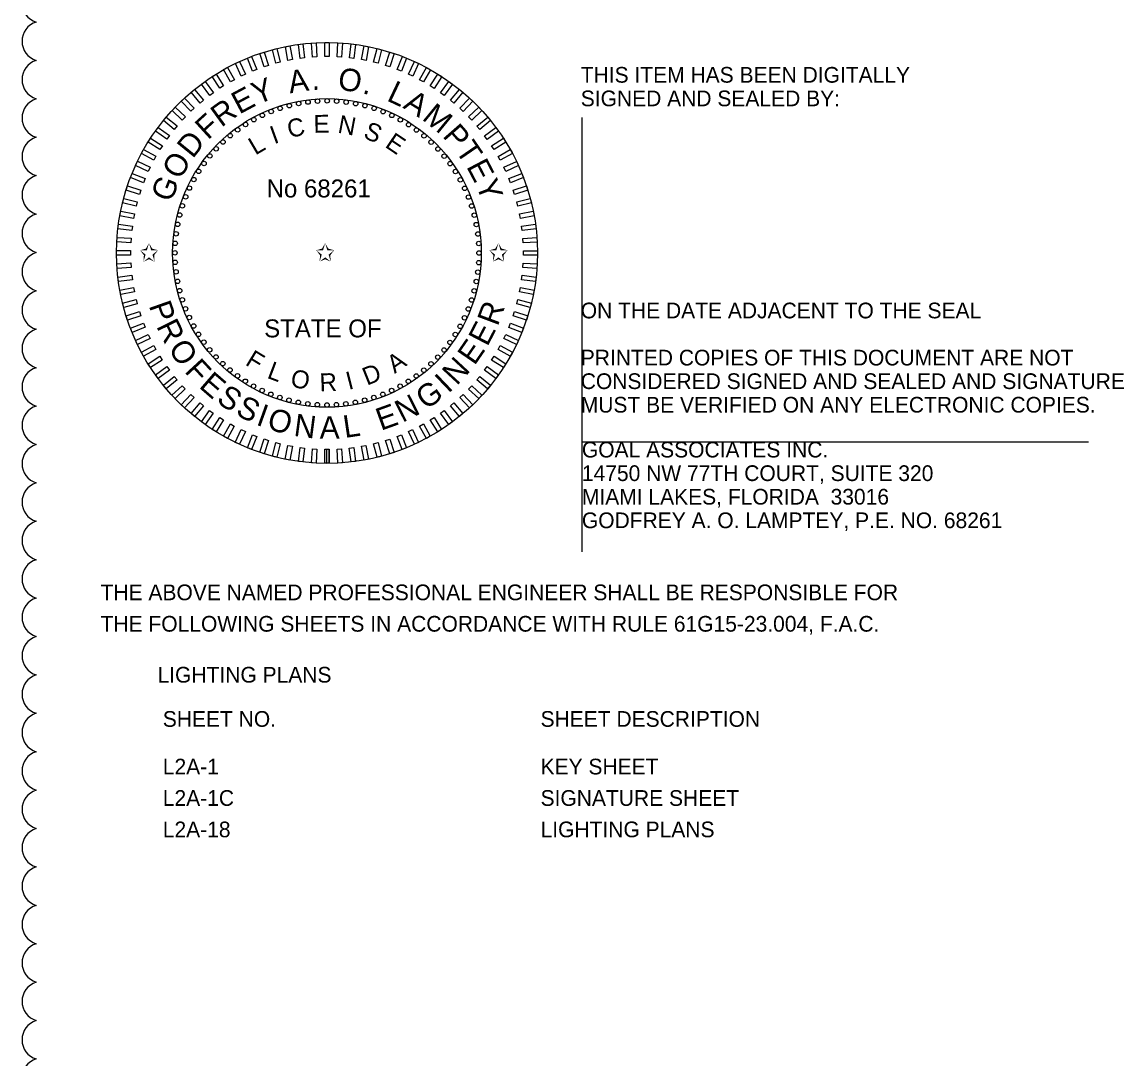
# Model space of a CAD drawing. Extents: x -811 to 10319, y -2309 to 9962.
# Drawn here: x -810.849 to -805.94, y -2224.471 to -2219.851 of the extents above; entities that cross this region are included whole.
import ezdxf

# ---------------------------------------------------------------- set-up
doc = ezdxf.new("R2010")
doc.units = 0
for name, color, linetype in [('AdhocPoint_dp', 7, 'Continuous'), ('PlotBorder_dp', 7, 'Continuous'), ('TextMinor', 7, 'Continuous'), ('TextMisc', 7, 'Continuous'), ('TextShtNo', 7, 'Continuous'), ('TextTitle', 7, 'Continuous')]:
    doc.layers.add(name, color=color, linetype=linetype)

msp = doc.modelspace()

# ---------------------------------------------------------------- linework, layer by layer
at = {"layer": 'AdhocPoint_dp'}
for p, q in [((-808.3546, -2220.2766), (-808.3546, -2222.2113)), ((-808.3546, -2221.7213), (-806.0979, -2221.7213))]:
    msp.add_line(p, q, dxfattribs=at)
at = {"layer": 'TextMinor'}
for radius in [0.9375, 0.6875]:
    msp.add_circle((-809.4901, -2220.88), radius, dxfattribs=at)
at = {"layer": 'TextShtNo'}
for p, q in [((-809.5001, -2221.8175), (-809.5003, -2221.755)), ((-809.4901, -2221.8175), (-809.4903, -2221.755)), ((-809.4801, -2221.8174), (-809.4803, -2221.7549))]:
    msp.add_line(p, q, dxfattribs=at)
for points in [[(-809.6441, -2220.0185), (-809.6639, -2220.0223), (-809.6756, -2219.961), (-809.6558, -2219.9572)], [(-809.5897, -2220.0105), (-809.6097, -2220.0131), (-809.6175, -2219.9511), (-809.5975, -2219.9486)], [(-809.5349, -2220.006), (-809.555, -2220.0073), (-809.559, -2219.945), (-809.5388, -2219.9437)], [(-809.4799, -2220.0049), (-809.5001, -2220.0049), (-809.5001, -2219.9425), (-809.4799, -2219.9425)], [(-809.425, -2220.0073), (-809.4452, -2220.006), (-809.4412, -2219.9437), (-809.4211, -2219.945)], [(-809.3703, -2220.0131), (-809.3904, -2220.0106), (-809.3825, -2219.9486), (-809.3625, -2219.9512)], [(-809.3162, -2220.0223), (-809.336, -2220.0186), (-809.3243, -2219.9572), (-809.3045, -2219.961)], [(-809.8028, -2220.0626), (-809.8215, -2220.0701), (-809.8445, -2220.012), (-809.8258, -2220.0046)], [(-809.7508, -2220.0446), (-809.77, -2220.0508), (-809.7893, -2219.9915), (-809.7701, -2219.9852)], [(-809.6979, -2220.0299), (-809.7174, -2220.0349), (-809.7329, -2219.9744), (-809.7134, -2219.9694)], [(-809.2626, -2220.0349), (-809.2822, -2220.0299), (-809.2667, -2219.9695), (-809.2471, -2219.9745)], [(-809.21, -2220.0509), (-809.2292, -2220.0447), (-809.2099, -2219.9853), (-809.1907, -2219.9915)], [(-809.1585, -2220.0701), (-809.1773, -2220.0627), (-809.1543, -2220.0046), (-809.1355, -2220.0121)], [(-809.9027, -2220.1083), (-809.9204, -2220.118), (-809.9505, -2220.0633), (-809.9328, -2220.0535)], [(-809.8535, -2220.0839), (-809.8717, -2220.0925), (-809.8983, -2220.036), (-809.8801, -2220.0274)], [(-809.1083, -2220.0925), (-809.1266, -2220.0839), (-809.1, -2220.0274), (-809.0817, -2220.036)], [(-809.0596, -2220.1181), (-809.0773, -2220.1083), (-809.0473, -2220.0536), (-809.0296, -2220.0634)], [(-809.9504, -2220.1357), (-809.9674, -2220.1465), (-810.0009, -2220.0938), (-809.9838, -2220.083)], [(-809.0127, -2220.1466), (-809.0297, -2220.1358), (-808.9962, -2220.0831), (-808.9792, -2220.0939)], [(-810.04, -2220.1992), (-810.0556, -2220.2121), (-810.0954, -2220.164), (-810.0798, -2220.1511)], [(-809.9962, -2220.1661), (-810.0125, -2220.1779), (-810.0492, -2220.1274), (-810.0329, -2220.1155)], [(-808.9676, -2220.178), (-808.9839, -2220.1662), (-808.9472, -2220.1156), (-808.9308, -2220.1275)], [(-808.9245, -2220.2122), (-808.9401, -2220.1994), (-808.9003, -2220.1512), (-808.8847, -2220.1641)], [(-810.0817, -2220.2351), (-810.0964, -2220.2489), (-810.1392, -2220.2034), (-810.1244, -2220.1896)], [(-808.8837, -2220.2491), (-808.8984, -2220.2352), (-808.8557, -2220.1897), (-808.841, -2220.2035)], [(-810.121, -2220.2735), (-810.1348, -2220.2882), (-810.1804, -2220.2455), (-810.1665, -2220.2308)], [(-808.8453, -2220.2884), (-808.8591, -2220.2737), (-808.8136, -2220.2309), (-808.7998, -2220.2456)], [(-810.1579, -2220.3143), (-810.1707, -2220.3299), (-810.2188, -2220.2901), (-810.206, -2220.2745)], [(-808.8094, -2220.33), (-808.8223, -2220.3145), (-808.7742, -2220.2747), (-808.7613, -2220.2902)], [(-810.192, -2220.3574), (-810.2039, -2220.3737), (-810.2544, -2220.337), (-810.2426, -2220.3207)], [(-808.7762, -2220.3739), (-808.7881, -2220.3575), (-808.7376, -2220.3208), (-808.7257, -2220.3372)], [(-810.2235, -2220.4025), (-810.2343, -2220.4195), (-810.287, -2220.3861), (-810.2762, -2220.369)], [(-808.7459, -2220.4197), (-808.7567, -2220.4026), (-808.7039, -2220.3692), (-808.6931, -2220.3862)], [(-810.252, -2220.4495), (-810.2617, -2220.4672), (-810.3164, -2220.4371), (-810.3067, -2220.4194)], [(-808.7184, -2220.4673), (-808.7281, -2220.4496), (-808.6734, -2220.4196), (-808.6637, -2220.4373)], [(-810.2775, -2220.4982), (-810.2861, -2220.5164), (-810.3426, -2220.4898), (-810.334, -2220.4716)], [(-808.694, -2220.5166), (-808.7026, -2220.4983), (-808.6461, -2220.4718), (-808.6375, -2220.49)], [(-810.3, -2220.5484), (-810.3074, -2220.5671), (-810.3654, -2220.5441), (-810.358, -2220.5254)], [(-808.6728, -2220.5673), (-808.6802, -2220.5485), (-808.6222, -2220.5256), (-808.6147, -2220.5443)], [(-810.3192, -2220.5999), (-810.3254, -2220.6191), (-810.3848, -2220.5998), (-810.3786, -2220.5806)], [(-808.6548, -2220.6192), (-808.661, -2220.6), (-808.6016, -2220.5808), (-808.5954, -2220.5999)], [(-810.3351, -2220.6525), (-810.3401, -2220.672), (-810.4006, -2220.6565), (-810.3956, -2220.637)], [(-808.64, -2220.6722), (-808.6451, -2220.6527), (-808.5846, -2220.6371), (-808.5796, -2220.6567)], [(-810.3477, -2220.706), (-810.3515, -2220.7258), (-810.4129, -2220.7141), (-810.4091, -2220.6943)], [(-808.6287, -2220.726), (-808.6325, -2220.7062), (-808.5711, -2220.6945), (-808.5673, -2220.7143)], [(-810.357, -2220.7602), (-810.3595, -2220.7802), (-810.4215, -2220.7724), (-810.4189, -2220.7524)], [(-808.6207, -2220.7804), (-808.6232, -2220.7604), (-808.5613, -2220.7525), (-808.5588, -2220.7726)], [(-810.3628, -2220.8148), (-810.3641, -2220.835), (-810.4264, -2220.8311), (-810.4251, -2220.8109)], [(-808.6162, -2220.8352), (-808.6174, -2220.815), (-808.5551, -2220.8111), (-808.5539, -2220.8313)], [(-810.3652, -2220.8698), (-810.3652, -2220.89), (-810.4276, -2220.89), (-810.4276, -2220.8698)], [(-808.6151, -2220.8901), (-808.6151, -2220.87), (-808.5527, -2220.87), (-808.5527, -2220.8901)], [(-810.3641, -2220.9247), (-810.3628, -2220.9449), (-810.4251, -2220.9488), (-810.4264, -2220.9287)], [(-808.6175, -2220.9451), (-808.6162, -2220.9249), (-808.5539, -2220.9288), (-808.5551, -2220.949)], [(-810.3595, -2220.9795), (-810.357, -2220.9995), (-810.4189, -2221.0074), (-810.4215, -2220.9873)], [(-808.6233, -2220.9997), (-808.6207, -2220.9797), (-808.5588, -2220.9875), (-808.5613, -2221.0076)], [(-810.3516, -2221.0339), (-810.3478, -2221.0537), (-810.4091, -2221.0654), (-810.4129, -2221.0456)], [(-808.6325, -2221.0539), (-808.6287, -2221.0341), (-808.5674, -2221.0458), (-808.5712, -2221.0656)], [(-810.3402, -2221.0877), (-810.3352, -2221.1073), (-810.3957, -2221.1228), (-810.4007, -2221.1032)], [(-808.6451, -2221.1074), (-808.6401, -2221.0879), (-808.5796, -2221.1034), (-808.5846, -2221.123)], [(-810.3255, -2221.1407), (-810.3192, -2221.1599), (-810.3786, -2221.1792), (-810.3849, -2221.16)], [(-808.6611, -2221.16), (-808.6548, -2221.1408), (-808.5954, -2221.1601), (-808.6017, -2221.1793)], [(-810.3075, -2221.1926), (-810.3, -2221.2114), (-810.3581, -2221.2344), (-810.3655, -2221.2156)], [(-808.6803, -2221.2115), (-808.6729, -2221.1928), (-808.6148, -2221.2158), (-808.6222, -2221.2345)], [(-810.2862, -2221.2433), (-810.2776, -2221.2616), (-810.3341, -2221.2882), (-810.3427, -2221.2699)], [(-808.7027, -2221.2617), (-808.6941, -2221.2435), (-808.6376, -2221.2701), (-808.6462, -2221.2883)], [(-810.2618, -2221.2926), (-810.2521, -2221.3103), (-810.3068, -2221.3403), (-810.3165, -2221.3227)], [(-808.7282, -2221.3104), (-808.7185, -2221.2927), (-808.6638, -2221.3228), (-808.6735, -2221.3405)], [(-810.2344, -2221.3402), (-810.2236, -2221.3573), (-810.2763, -2221.3907), (-810.2871, -2221.3737)], [(-808.7568, -2221.3574), (-808.746, -2221.3404), (-808.6932, -2221.3738), (-808.704, -2221.3909)], [(-810.204, -2221.386), (-810.1922, -2221.4024), (-810.2427, -2221.4391), (-810.2545, -2221.4227)], [(-810.1708, -2221.4299), (-810.158, -2221.4454), (-810.2061, -2221.4852), (-810.2189, -2221.4697)], [(-808.8224, -2221.4456), (-808.8095, -2221.43), (-808.7614, -2221.4698), (-808.7743, -2221.4854)], [(-808.7882, -2221.4025), (-808.7763, -2221.3862), (-808.7258, -2221.4229), (-808.7377, -2221.4392)], [(-810.135, -2221.4715), (-810.1211, -2221.4862), (-810.1667, -2221.529), (-810.1805, -2221.5143)], [(-808.8592, -2221.4864), (-808.8454, -2221.4717), (-808.7999, -2221.5144), (-808.8137, -2221.5291)], [(-810.0965, -2221.5109), (-810.0818, -2221.5247), (-810.1246, -2221.5702), (-810.1393, -2221.5564)], [(-808.8985, -2221.5248), (-808.8838, -2221.511), (-808.8411, -2221.5565), (-808.8558, -2221.5703)], [(-810.0557, -2221.5477), (-810.0402, -2221.5606), (-810.08, -2221.6087), (-810.0955, -2221.5958)], [(-808.9402, -2221.5607), (-808.9247, -2221.5478), (-808.8848, -2221.5959), (-808.9004, -2221.6088)], [(-810.0127, -2221.5819), (-809.9964, -2221.5937), (-810.0331, -2221.6443), (-810.0494, -2221.6324)], [(-809.9676, -2221.6133), (-809.9505, -2221.6241), (-809.984, -2221.6768), (-810.001, -2221.666)], [(-809.0299, -2221.6242), (-809.0128, -2221.6134), (-808.9794, -2221.6661), (-808.9964, -2221.6769)], [(-808.984, -2221.5939), (-808.9677, -2221.582), (-808.931, -2221.6325), (-808.9473, -2221.6444)], [(-809.9206, -2221.6418), (-809.9029, -2221.6516), (-809.933, -2221.7063), (-809.9507, -2221.6966)], [(-809.8719, -2221.6674), (-809.8536, -2221.676), (-809.8802, -2221.7325), (-809.8985, -2221.7239)], [(-809.1268, -2221.676), (-809.1085, -2221.6674), (-809.0819, -2221.7239), (-809.1002, -2221.7325)], [(-809.0775, -2221.6517), (-809.0598, -2221.6419), (-809.0297, -2221.6966), (-809.0474, -2221.7064)], [(-809.8217, -2221.6898), (-809.8029, -2221.6972), (-809.8259, -2221.7553), (-809.8447, -2221.7478)], [(-809.7702, -2221.709), (-809.751, -2221.7152), (-809.7703, -2221.7746), (-809.7895, -2221.7684)], [(-809.7176, -2221.725), (-809.698, -2221.73), (-809.7136, -2221.7905), (-809.7331, -2221.7854)], [(-809.2824, -2221.73), (-809.2628, -2221.725), (-809.2473, -2221.7855), (-809.2668, -2221.7905)], [(-809.2294, -2221.7153), (-809.2102, -2221.7091), (-809.1909, -2221.7685), (-809.2101, -2221.7747)], [(-809.1775, -2221.6973), (-809.1587, -2221.6899), (-809.1357, -2221.7479), (-809.1545, -2221.7553)], [(-809.6641, -2221.7376), (-809.6443, -2221.7414), (-809.656, -2221.8027), (-809.6758, -2221.7989)], [(-809.6099, -2221.7468), (-809.5899, -2221.7493), (-809.5977, -2221.8113), (-809.6177, -2221.8088)], [(-809.5552, -2221.7526), (-809.5351, -2221.7539), (-809.539, -2221.8162), (-809.5592, -2221.8149)], [(-809.5003, -2221.755), (-809.4801, -2221.755), (-809.4801, -2221.8174), (-809.5003, -2221.8174)], [(-809.4453, -2221.7539), (-809.4252, -2221.7526), (-809.4213, -2221.8149), (-809.4414, -2221.8162)], [(-809.3906, -2221.7494), (-809.3705, -2221.7468), (-809.3627, -2221.8088), (-809.3827, -2221.8113)], [(-809.3362, -2221.7414), (-809.3163, -2221.7376), (-809.3046, -2221.7989), (-809.3245, -2221.8027)]]:
    msp.add_lwpolyline(points, close=True, dxfattribs=at)
for centre in [(-809.5745, -2220.2078), (-809.5321, -2220.2038), (-809.4896, -2220.2025), (-809.447, -2220.2039), (-809.4047, -2220.2079), (-809.739, -2220.2499), (-809.6989, -2220.2355), (-809.6581, -2220.2236), (-809.6165, -2220.2144), (-809.3626, -2220.2146), (-809.3211, -2220.2239), (-809.2802, -2220.2358), (-809.2402, -2220.2503), (-809.8527, -2220.3076), (-809.816, -2220.286), (-809.7781, -2220.2667), (-809.2012, -2220.2672), (-809.1633, -2220.2866), (-809.1266, -2220.3083), (-809.9215, -2220.3576), (-809.8879, -2220.3315), (-809.0915, -2220.3322), (-809.0579, -2220.3583), (-809.9535, -2220.3857), (-809.026, -2220.3865), (-810.0118, -2220.4477), (-809.9836, -2220.4158), (-808.9959, -2220.4166), (-808.9678, -2220.4486), (-810.0379, -2220.4813), (-808.9417, -2220.4822), (-810.0835, -2220.5531), (-810.0618, -2220.5165), (-808.9178, -2220.5174), (-808.8962, -2220.5541), (-810.1029, -2220.591), (-808.8769, -2220.592), (-810.1198, -2220.63), (-808.86, -2220.6311), (-810.1343, -2220.6701), (-808.8456, -2220.6711), (-810.1555, -2220.7525), (-810.1462, -2220.7109), (-808.8338, -2220.712), (-808.8245, -2220.7536), (-810.1622, -2220.7945), (-808.8179, -2220.7956), (-810.1662, -2220.8369), (-808.814, -2220.838), (-810.1676, -2220.8794), (-808.8127, -2220.8805), (-810.1663, -2220.9219), (-808.814, -2220.9231), (-810.1623, -2220.9643), (-808.8181, -2220.9654), (-810.1557, -2221.0063), (-810.1464, -2221.0479), (-808.8248, -2221.0075), (-810.1346, -2221.0888), (-808.846, -2221.0898), (-808.8341, -2221.049), (-810.1202, -2221.1288), (-808.8604, -2221.1299), (-810.1034, -2221.1679), (-808.8774, -2221.1689), (-810.0841, -2221.2058), (-810.0624, -2221.2425), (-808.9184, -2221.2434), (-808.8967, -2221.2068), (-810.0385, -2221.2777), (-808.9424, -2221.2786), (-810.0125, -2221.3114), (-808.9685, -2221.3122), (-809.9844, -2221.3433), (-809.9543, -2221.3734), (-809.0268, -2221.3742), (-808.9967, -2221.3441), (-809.9224, -2221.4016), (-809.8888, -2221.4277), (-809.0924, -2221.4284), (-809.0587, -2221.4023), (-809.8536, -2221.4517), (-809.817, -2221.4734), (-809.1642, -2221.4739), (-809.1276, -2221.4523), (-809.7791, -2221.4927), (-809.74, -2221.5096), (-809.7, -2221.5241), (-809.6591, -2221.536), (-809.3222, -2221.5363), (-809.2813, -2221.5244), (-809.2413, -2221.5101), (-809.2022, -2221.4932), (-809.6176, -2221.5453), (-809.5756, -2221.552), (-809.5332, -2221.5561), (-809.4901, -2221.5575), (-809.4481, -2221.5561), (-809.4058, -2221.5522), (-809.3637, -2221.5455)]:
    msp.add_circle(centre, 0.01, dxfattribs=at)
at = {"layer": 'TextTitle'}
for centre in [(-810.7588, -2219.7655), (-810.7588, -2219.9367), (-810.7588, -2220.1078), (-810.7588, -2220.2789), (-810.7588, -2220.45), (-810.7588, -2220.6212), (-810.7588, -2220.7923), (-810.7588, -2220.9634), (-810.7588, -2221.1345), (-810.7588, -2221.3057), (-810.7588, -2221.4768), (-810.7588, -2221.6479), (-810.7588, -2221.819), (-810.7588, -2221.9901), (-810.7588, -2222.1613), (-810.7588, -2222.3324), (-810.7588, -2222.5035), (-810.7588, -2222.6746), (-810.7588, -2222.8458), (-810.7588, -2223.0169), (-810.7588, -2223.188), (-810.7588, -2223.3591), (-810.7588, -2223.5302), (-810.7588, -2223.7014), (-810.7588, -2223.8725), (-810.7588, -2224.0436), (-810.7588, -2224.2147), (-810.7588, -2224.3859), (-810.7588, -2224.557)]:
    msp.add_arc(centre, 0.0897, 107.5, 252.5, dxfattribs=at)

# ---------------------------------------------------------------- texts
at = {"layer": 'PlotBorder_dp'}
for s, p in [('THIS ITEM HAS BEEN DIGITALLY', (-808.3596, -2220.1214)), ('SIGNED AND SEALED BY:', (-808.3596, -2220.2264)), ('ON THE DATE ADJACENT TO THE SEAL', (-808.3596, -2221.1714)), ('PRINTED COPIES OF THIS DOCUMENT ARE NOT ', (-808.3596, -2221.3814)), ('CONSIDERED SIGNED AND SEALED AND SIGNATURE ', (-808.3596, -2221.4864)), ('MUST BE VERIFIED ON ANY ELECTRONIC COPIES.', (-808.3596, -2221.5914)), ('GOAL ASSOCIATES INC.', (-808.3546, -2221.7913)), ('14750 NW 77TH COURT, SUITE 320', (-808.3546, -2221.8963)), ('MIAMI LAKES, FLORIDA  33016', (-808.3546, -2222.0013)), ('GODFREY A. O. LAMPTEY, P.E. NO. 68261', (-808.3546, -2222.1063)), ('THE ABOVE NAMED PROFESSIONAL ENGINEER SHALL BE RESPONSIBLE FOR ', (-810.4987, -2222.4274)), ('THE FOLLOWING SHEETS IN ACCORDANCE WITH RULE 61G15-23.004, F.A.C.', (-810.4987, -2222.5674)), ('LIGHTING PLANS', (-810.245, -2222.7944))]:
    msp.add_text(s, height=0.07, dxfattribs=at).set_placement(p)
at = {"layer": 'TextMisc'}
for s, p in [('SHEET NO.', (-810.2215, -2222.9914)), ('SHEET DESCRIPTION', (-808.5387, -2222.9914)), ('L2A-1', (-810.2215, -2223.2036)), ('KEY SHEET', (-808.5387, -2223.2036)), ('L2A-1C', (-810.2215, -2223.3436)), ('SIGNATURE SHEET', (-808.5387, -2223.3436)), ('L2A-18', (-810.2215, -2223.4836)), ('LIGHTING PLANS', (-808.5387, -2223.4836))]:
    msp.add_text(s, height=0.07, dxfattribs=at).set_placement(p)
at = {"layer": 'TextShtNo'}
for s, height, rotation, p in [('O', 0.1, 352.1877, (-809.4449, -2220.1518)), ('Y', 0.1, 21.0633, (-809.8021, -2220.2205)), ('A', 0.1, 8.8088, (-809.6551, -2220.1693)), ('E', 0.1, 28.1055, (-809.8806, -2220.2638)), ('.', 0.1, 1.0418, (-809.5575, -2220.1536)), ('L', 0.1, 334.6727, (-809.2279, -2220.1992)), ('R', 0.1, 35.9269, (-809.9609, -2220.3226)), ('.', 0.1, 343.5268, (-809.3358, -2220.167)), ('A', 0.1, 328.4096, (-809.1552, -2220.2319)), ('M', 0.1, 320.6426, (-809.0707, -2220.2831)), ('F', 0.1, 42.3772, (-810.0205, -2220.3791)), ('C', 0.08, 12.2025, (-809.6579, -2220.3684)), ('E', 0.08, 0.4186, (-809.5498, -2220.3449)), ('N', 0.08, 349.2914, (-809.4455, -2220.3434)), ('S', 0.08, 337.0221, (-809.3325, -2220.3652)), ('D', 0.1, 50.8569, (-810.0886, -2220.4627)), ('I', 0.08, 20.0117, (-809.7258, -2220.3959)), ('E', 0.08, 325.8663, (-809.2358, -2220.4054)), ('P', 0.1, 311.1966, (-808.9784, -2220.36)), ('L', 0.08, 30.4021, (-809.8093, -2220.4463)), ('T', 0.1, 304.4563, (-808.9209, -2220.4237)), ('O', 0.1, 59.5178, (-810.1446, -2220.5576)), ('E', 0.1, 297.6315, (-808.8707, -2220.4946)), ('G', 0.1, 68.0518, (-810.1851, -2220.6583)), ('Y', 0.1, 290.5893, (-808.8281, -2220.5734)), ('P', 0.1, 289.4055, (-810.2848, -2221.1145)), ('R', 0.1, 69.5134, (-808.7299, -2221.2097)), ('R', 0.1, 296.1458, (-810.2518, -2221.2062)), ('E', 0.1, 62.4712, (-808.7761, -2221.3004)), ('O', 0.1, 303.9671, (-810.2003, -2221.3068)), ('E', 0.1, 55.4289, (-808.833, -2221.3847)), ('F', 0.08, 328.7241, (-809.8582, -2221.3765)), ('A', 0.08, 34.4992, (-809.1883, -2221.4194)), ('F', 0.1, 312.628, (-810.1279, -2221.4089)), ('L', 0.08, 339.2916, (-809.7609, -2221.4356)), ('D', 0.08, 22.0128, (-809.312, -2221.4719)), ('N', 0.1, 47.1788, (-808.9123, -2221.4738)), ('E', 0.1, 319.0783, (-810.0645, -2221.4772)), ('O', 0.08, 349.6821, (-809.6562, -2221.4753)), ('R', 0.08, 2.3398, (-809.5217, -2221.4973)), ('I', 0.08, 14.2037, (-809.3941, -2221.4906)), ('I', 0.1, 43.6456, (-808.9499, -2221.5083)), ('S', 0.1, 326.1206, (-809.9869, -2221.5431)), ('G', 0.1, 35.1115, (-809.0492, -2221.5815)), ('S', 0.1, 333.193, (-809.9015, -2221.5992)), ('N', 0.1, 26.8614, (-809.1544, -2221.6375)), ('I', 0.1, 340.2654, (-809.8098, -2221.6444)), ('O', 0.1, 343.7986, (-809.7621, -2221.6627)), ('E', 0.1, 19.8191, (-809.2498, -2221.6729)), ('N', 0.1, 352.4595, (-809.6411, -2221.6947)), ('A', 0.1, 0.7097, (-809.5227, -2221.7079)), ('L', 0.1, 8.4767, (-809.4105, -2221.7047))]:
    msp.add_text(s, height=height, rotation=rotation, dxfattribs=at).set_placement(p)
for s, p in [('No 68261', (-809.7591, -2220.6327)), ('✩', (-810.3251, -2220.9179)), ('✩', (-809.5404, -2220.9179)), ('✩', (-808.7685, -2220.9179)), ('STATE OF', (-809.7698, -2221.2562))]:
    msp.add_text(s, height=0.08, dxfattribs=at).set_placement(p)

doc.saveas('drawing.dxf')
